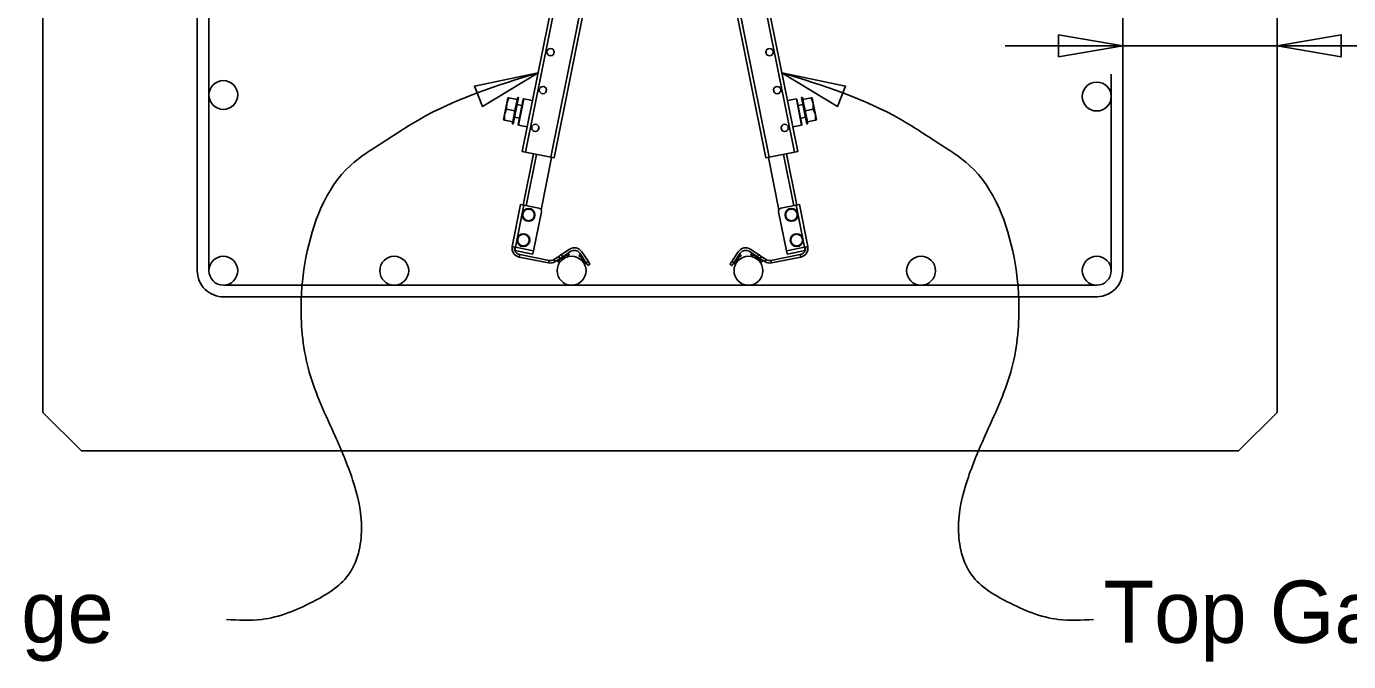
# Model space of a CAD drawing. Extents: x 0 to 36.1, y -3.7 to 15.
# Drawn here: x 2.266 to 4.409, y 2.071 to 3.1 of the extents above; entities that cross this region are included whole.
import ezdxf

# ---------------------------------------------------------------- set-up
doc = ezdxf.new("R2010")
doc.units = 0
for name, color, linetype in [('Leader', 7, 'Continuous'), ('Miscellaneous', 7, 'Continuous'), ('PileConc', 7, 'Continuous'), ('PlotBorder_dp', 7, 'Continuous'), ('PrestressSteel', 7, 'Continuous')]:
    doc.layers.add(name, color=color, linetype=linetype)

msp = doc.modelspace()

# ---------------------------------------------------------------- linework, layer by layer
at = {"layer": 'Leader'}
for points in [[(2.5903, 2.1388), (2.6477, 2.1388), (2.7303, 2.1675), (2.7877, 2.2106), (2.8093, 2.2859), (2.7949, 2.3649), (2.7662, 2.4367), (2.7246, 2.5398), (2.7114, 2.6484), (2.7193, 2.7252), (2.7913, 2.8747), (2.8439, 2.912), (2.903, 2.9492), (3.0957, 3.0249)], [(3.9958, 2.1388), (3.9383, 2.1388), (3.8558, 2.1675), (3.7983, 2.2106), (3.7768, 2.2859), (3.7912, 2.3649), (3.8199, 2.4367), (3.8615, 2.5398), (3.8747, 2.6484), (3.8668, 2.7252), (3.7947, 2.8747), (3.7422, 2.912), (3.6831, 2.9492), (3.4904, 3.0249)]]:
    msp.add_spline(points, degree=3, dxfattribs=at)
at = {"layer": 'Miscellaneous'}
for p, q in [((3.5162, 2.8971), (3.3195, 3.8739)), ((3.0699, 2.8971), (3.2126, 3.6058)), ((3.0751, 2.896), (3.1768, 3.4012)), ((3.1161, 2.8878), (3.2173, 3.3902)), ((3.1213, 2.8867), (3.2224, 3.3892)), ((3.4648, 2.8867), (3.3637, 3.3892)), ((3.47, 2.8878), (3.3688, 3.3902)), ((3.511, 2.896), (3.4093, 3.4012)), ((3.1203, 3.0546), (3.1214, 3.0597)), ((3.4658, 3.0546), (3.4647, 3.0597)), ((3.0447, 2.9753), (3.0465, 2.9843)), ((3.0481, 2.984), (3.0447, 2.9753)), ((3.0465, 2.9843), (3.0481, 2.984)), ((3.0615, 2.9813), (3.0481, 2.984)), ((3.0624, 2.9848), (3.0538, 2.9418)), ((3.055, 2.9416), (3.0636, 2.9846)), ((3.0615, 2.9813), (3.0579, 2.9633)), ((3.0611, 2.9814), (3.0624, 2.9848)), ((3.0624, 2.9848), (3.0636, 2.9846)), ((3.0713, 2.9821), (3.063, 2.9409)), ((3.0635, 2.9401), (3.0721, 2.9826)), ((3.0721, 2.9826), (3.0866, 2.9797)), ((3.108, 2.9932), (3.109, 2.9984)), ((3.4781, 2.9932), (3.4771, 2.9984)), ((3.514, 2.9826), (3.4995, 2.9797)), ((3.5226, 2.9401), (3.514, 2.9826)), ((3.5148, 2.9821), (3.5231, 2.9409)), ((3.5237, 2.9848), (3.5225, 2.9846)), ((3.5311, 2.9416), (3.5225, 2.9846)), ((3.525, 2.9814), (3.5237, 2.9848)), ((3.5237, 2.9848), (3.5323, 2.9418)), ((3.5245, 2.9813), (3.5379, 2.984)), ((3.5245, 2.9813), (3.5281, 2.9633)), ((3.5395, 2.9843), (3.5379, 2.984)), ((3.5379, 2.984), (3.5413, 2.9753)), ((3.5413, 2.9753), (3.5395, 2.9843)), ((3.0393, 2.9485), (3.0411, 2.9574)), ((3.0411, 2.9574), (3.0447, 2.9753)), ((3.0445, 2.966), (3.0411, 2.9574)), ((3.0579, 2.9633), (3.0445, 2.966)), ((3.0579, 2.9633), (3.0543, 2.9454)), ((3.0614, 2.9733), (3.0692, 2.9717)), ((3.5247, 2.9733), (3.5169, 2.9717)), ((3.5281, 2.9633), (3.5415, 2.966)), ((3.5281, 2.9633), (3.5318, 2.9454)), ((3.545, 2.9574), (3.5413, 2.9753)), ((3.5415, 2.966), (3.545, 2.9574)), ((3.5468, 2.9485), (3.545, 2.9574)), ((3.0409, 2.9481), (3.0393, 2.9485)), ((3.0543, 2.9454), (3.0409, 2.9481)), ((3.0538, 2.9418), (3.0538, 2.9455)), ((3.055, 2.9416), (3.0538, 2.9418)), ((3.0651, 2.9513), (3.0572, 2.9528)), ((3.078, 2.9372), (3.0635, 2.9401)), ((3.0956, 2.9318), (3.0966, 2.937)), ((3.4905, 2.9318), (3.4894, 2.937)), ((3.5081, 2.9372), (3.5226, 2.9401)), ((3.521, 2.9513), (3.5288, 2.9528)), ((3.5311, 2.9416), (3.5323, 2.9418)), ((3.5318, 2.9454), (3.5452, 2.9481)), ((3.5323, 2.9418), (3.5322, 2.9455)), ((3.5452, 2.9481), (3.5468, 2.9485)), ((3.0751, 2.896), (3.0699, 2.8971)), ((3.0712, 2.8104), (3.0879, 2.8934)), ((3.0751, 2.896), (3.1161, 2.8878)), ((3.511, 2.896), (3.47, 2.8878)), ((3.5149, 2.8104), (3.4982, 2.8934)), ((3.511, 2.896), (3.5162, 2.8971)), ((3.0763, 2.8093), (3.093, 2.8924)), ((3.1003, 2.8028), (3.1173, 2.8875)), ((3.1213, 2.8867), (3.1161, 2.8878)), ((3.4648, 2.8867), (3.47, 2.8878)), ((3.4858, 2.8028), (3.4687, 2.8875)), ((3.5098, 2.8093), (3.493, 2.8924)), ((3.0535, 2.7431), (3.0672, 2.8112)), ((3.0587, 2.7421), (3.0724, 2.8101)), ((3.0672, 2.8112), (3.0724, 2.8101)), ((3.0969, 2.8052), (3.0724, 2.8101)), ((3.4891, 2.8052), (3.5137, 2.8101)), ((3.5189, 2.8112), (3.5137, 2.8101)), ((3.5274, 2.7421), (3.5137, 2.8101)), ((3.5326, 2.7431), (3.5189, 2.8112)), ((3.0882, 2.7362), (3.1009, 2.7993)), ((3.4979, 2.7362), (3.4852, 2.7993)), ((3.0587, 2.7421), (3.0535, 2.7431)), ((3.5274, 2.7421), (3.5326, 2.7431)), ((3.0577, 2.7369), (3.0587, 2.7421)), ((3.0871, 2.731), (3.0577, 2.7369)), ((3.0587, 2.7421), (3.0882, 2.7362)), ((3.0656, 2.7301), (3.0648, 2.7261)), ((3.1124, 2.7166), (3.0648, 2.7261)), ((3.1132, 2.7205), (3.0656, 2.7301)), ((3.0882, 2.7362), (3.0871, 2.731)), ((3.1289, 2.7273), (3.121, 2.722)), ((3.121, 2.722), (3.1232, 2.7187)), ((3.1311, 2.7239), (3.1232, 2.7187)), ((3.1311, 2.7239), (3.1289, 2.7273)), ((3.1296, 2.7214), (3.1307, 2.7197)), ((3.1462, 2.7388), (3.133, 2.73)), ((3.133, 2.73), (3.1353, 2.7267)), ((3.1337, 2.7242), (3.1349, 2.7225)), ((3.1353, 2.7267), (3.1485, 2.7355)), ((3.136, 2.7272), (3.1367, 2.7261)), ((3.1362, 2.7258), (3.1374, 2.7241)), ((3.1379, 2.727), (3.1391, 2.7252)), ((3.1421, 2.7297), (3.1432, 2.728)), ((3.1443, 2.7327), (3.145, 2.7317)), ((3.1446, 2.7314), (3.1457, 2.7296)), ((3.1633, 2.7298), (3.1615, 2.7287)), ((3.1629, 2.7326), (3.1736, 2.7166)), ((3.163, 2.7303), (3.164, 2.731)), ((3.1649, 2.7274), (3.1632, 2.7262)), ((3.1665, 2.725), (3.1648, 2.7238)), ((3.1662, 2.7254), (3.1672, 2.7261)), ((3.1769, 2.7188), (3.1663, 2.7348)), ((3.1681, 2.7225), (3.1664, 2.7213)), ((3.4092, 2.7188), (3.4198, 2.7348)), ((3.4232, 2.7326), (3.4125, 2.7166)), ((3.418, 2.7225), (3.4197, 2.7213)), ((3.4199, 2.7254), (3.4189, 2.7261)), ((3.4196, 2.725), (3.4213, 2.7238)), ((3.4212, 2.7274), (3.4229, 2.7262)), ((3.4231, 2.7303), (3.4221, 2.731)), ((3.4228, 2.7298), (3.4246, 2.7287)), ((3.4508, 2.7267), (3.4376, 2.7355)), ((3.4398, 2.7388), (3.4531, 2.73)), ((3.4415, 2.7314), (3.4404, 2.7296)), ((3.4418, 2.7327), (3.4411, 2.7317)), ((3.444, 2.7297), (3.4428, 2.728)), ((3.4482, 2.727), (3.447, 2.7252)), ((3.4499, 2.7258), (3.4487, 2.7241)), ((3.4501, 2.7272), (3.4494, 2.7261)), ((3.4531, 2.73), (3.4508, 2.7267)), ((3.4523, 2.7242), (3.4512, 2.7225)), ((3.455, 2.7239), (3.4572, 2.7273)), ((3.455, 2.7239), (3.4629, 2.7187)), ((3.4565, 2.7214), (3.4554, 2.7197)), ((3.4572, 2.7273), (3.4651, 2.722)), ((3.4651, 2.722), (3.4629, 2.7187)), ((3.4729, 2.7205), (3.5204, 2.7301)), ((3.4737, 2.7166), (3.5212, 2.7261)), ((3.5274, 2.7421), (3.4979, 2.7362)), ((3.4979, 2.7362), (3.499, 2.731)), ((3.499, 2.731), (3.5284, 2.7369)), ((3.5204, 2.7301), (3.5212, 2.7261)), ((3.5284, 2.7369), (3.5274, 2.7421)), ((3.1124, 2.7166), (3.1132, 2.7205)), ((3.1267, 2.7195), (3.126, 2.7205)), ((3.1271, 2.7198), (3.1283, 2.718)), ((3.1693, 2.7207), (3.1676, 2.7196)), ((3.1709, 2.7183), (3.1692, 2.7172)), ((3.1725, 2.7159), (3.1708, 2.7147)), ((3.1739, 2.7161), (3.1728, 2.7154)), ((3.1736, 2.7166), (3.1769, 2.7188)), ((3.1797, 2.7146), (3.1763, 2.7124)), ((3.4064, 2.7146), (3.4097, 2.7124)), ((3.4125, 2.7166), (3.4092, 2.7188)), ((3.4122, 2.7161), (3.4132, 2.7154)), ((3.4135, 2.7159), (3.4153, 2.7147)), ((3.4152, 2.7183), (3.4169, 2.7172)), ((3.4168, 2.7207), (3.4185, 2.7196)), ((3.459, 2.7198), (3.4578, 2.718)), ((3.4594, 2.7195), (3.4601, 2.7205)), ((3.4737, 2.7166), (3.4729, 2.7205))]:
    msp.add_line(p, q, dxfattribs=at)
for points in [[(3.0411, 2.9574), (3.041, 2.9568), (3.0409, 2.9481)], [(3.0447, 2.9753), (3.0446, 2.9747), (3.0445, 2.966)], [(3.5413, 2.9753), (3.5415, 2.9747), (3.5415, 2.966)], [(3.545, 2.9574), (3.5451, 2.9568), (3.5452, 2.9481)], [(3.1289, 2.7273), (3.1289, 2.7273), (3.1292, 2.7275), (3.1296, 2.7277), (3.1301, 2.7281), (3.1307, 2.7285), (3.1314, 2.729), (3.1322, 2.7295), (3.133, 2.73)], [(3.1337, 2.7242), (3.1332, 2.7239), (3.1327, 2.7235), (3.1322, 2.7232), (3.1317, 2.7228), (3.1311, 2.7225), (3.1306, 2.7221), (3.1301, 2.7218), (3.1296, 2.7214)], [(3.1353, 2.7267), (3.1344, 2.7262), (3.1337, 2.7256), (3.1329, 2.7252), (3.1323, 2.7247), (3.1318, 2.7244), (3.1314, 2.7241), (3.1312, 2.724), (3.1311, 2.7239)], [(3.1374, 2.7241), (3.1372, 2.724), (3.1369, 2.7238), (3.1367, 2.7236), (3.1364, 2.7234), (3.136, 2.7232), (3.1357, 2.723), (3.1353, 2.7227), (3.1349, 2.7225)], [(3.1367, 2.7261), (3.1366, 2.7261), (3.1366, 2.7261), (3.1364, 2.726), (3.1362, 2.7258)], [(3.1391, 2.7252), (3.1387, 2.725), (3.1383, 2.7247), (3.138, 2.7245), (3.1376, 2.7243), (3.1374, 2.7241)], [(3.1421, 2.7297), (3.1416, 2.7294), (3.1411, 2.7291), (3.1405, 2.7287), (3.14, 2.7284), (3.1395, 2.728), (3.1389, 2.7277), (3.1384, 2.7273), (3.1379, 2.727)], [(3.1457, 2.7296), (3.1455, 2.7295), (3.1453, 2.7294), (3.145, 2.7292), (3.1447, 2.729), (3.1444, 2.7288), (3.144, 2.7285), (3.1436, 2.7283), (3.1432, 2.728)], [(3.145, 2.7317), (3.145, 2.7317), (3.1449, 2.7316), (3.1448, 2.7315), (3.1446, 2.7314)], [(3.1632, 2.7262), (3.1629, 2.7266), (3.1626, 2.727), (3.1624, 2.7273), (3.1622, 2.7277), (3.162, 2.728), (3.1618, 2.7282), (3.1617, 2.7285), (3.1615, 2.7287)], [(3.1633, 2.7298), (3.1631, 2.73), (3.163, 2.7302), (3.163, 2.7303), (3.163, 2.7303)], [(3.1664, 2.7213), (3.1661, 2.7217), (3.1659, 2.7221), (3.1656, 2.7225), (3.1654, 2.7228), (3.1652, 2.7231), (3.165, 2.7234), (3.1649, 2.7236), (3.1648, 2.7238)], [(3.1662, 2.7254), (3.1659, 2.7258), (3.1656, 2.7263), (3.1652, 2.7269), (3.1649, 2.7274)], [(3.1665, 2.725), (3.1664, 2.7252), (3.1663, 2.7253), (3.1662, 2.7254), (3.1662, 2.7254)], [(3.1676, 2.7196), (3.1674, 2.7198), (3.1673, 2.72), (3.1671, 2.7203), (3.1669, 2.7206), (3.1667, 2.7209), (3.1664, 2.7213), (3.1664, 2.7213)], [(3.1709, 2.7183), (3.1706, 2.7188), (3.1702, 2.7193), (3.1699, 2.7199), (3.1695, 2.7204), (3.1692, 2.7209), (3.1688, 2.7215), (3.1685, 2.722), (3.1681, 2.7225)], [(3.4152, 2.7183), (3.4155, 2.7188), (3.4159, 2.7193), (3.4162, 2.7199), (3.4166, 2.7204), (3.4169, 2.7209), (3.4173, 2.7215), (3.4176, 2.722), (3.418, 2.7225)], [(3.4185, 2.7196), (3.4186, 2.7198), (3.4188, 2.72), (3.419, 2.7203), (3.4192, 2.7206), (3.4194, 2.7209), (3.4196, 2.7213), (3.4197, 2.7213)], [(3.4196, 2.725), (3.4197, 2.7252), (3.4198, 2.7253), (3.4199, 2.7254), (3.4199, 2.7254)], [(3.4197, 2.7213), (3.42, 2.7217), (3.4202, 2.7221), (3.4204, 2.7225), (3.4207, 2.7228), (3.4209, 2.7231), (3.421, 2.7234), (3.4212, 2.7236), (3.4213, 2.7238)], [(3.4199, 2.7254), (3.4202, 2.7258), (3.4205, 2.7263), (3.4209, 2.7269), (3.4212, 2.7274)], [(3.4228, 2.7298), (3.423, 2.73), (3.4231, 2.7302), (3.4231, 2.7303), (3.4231, 2.7303)], [(3.4229, 2.7262), (3.4232, 2.7266), (3.4234, 2.727), (3.4237, 2.7273), (3.4239, 2.7277), (3.4241, 2.728), (3.4243, 2.7282), (3.4244, 2.7285), (3.4246, 2.7287)], [(3.4404, 2.7296), (3.4406, 2.7295), (3.4408, 2.7294), (3.4411, 2.7292), (3.4414, 2.729), (3.4417, 2.7288), (3.4421, 2.7285), (3.4424, 2.7283), (3.4428, 2.728)], [(3.4411, 2.7317), (3.4411, 2.7317), (3.4412, 2.7316), (3.4413, 2.7315), (3.4415, 2.7314)], [(3.444, 2.7297), (3.4445, 2.7294), (3.445, 2.7291), (3.4455, 2.7287), (3.4461, 2.7284), (3.4466, 2.728), (3.4471, 2.7277), (3.4477, 2.7273), (3.4482, 2.727)], [(3.447, 2.7252), (3.4474, 2.725), (3.4478, 2.7247), (3.4481, 2.7245), (3.4485, 2.7243), (3.4487, 2.7241)], [(3.4487, 2.7241), (3.4489, 2.724), (3.4492, 2.7238), (3.4494, 2.7236), (3.4497, 2.7234), (3.4501, 2.7232), (3.4504, 2.723), (3.4508, 2.7227), (3.4512, 2.7225)], [(3.4494, 2.7261), (3.4494, 2.7261), (3.4495, 2.7261), (3.4497, 2.726), (3.4499, 2.7258)], [(3.4508, 2.7267), (3.4516, 2.7262), (3.4524, 2.7256), (3.4531, 2.7252), (3.4538, 2.7247), (3.4543, 2.7244), (3.4547, 2.7241), (3.4549, 2.724), (3.455, 2.7239)], [(3.4523, 2.7242), (3.4528, 2.7239), (3.4534, 2.7235), (3.4539, 2.7232), (3.4544, 2.7228), (3.455, 2.7225), (3.4555, 2.7221), (3.456, 2.7218), (3.4565, 2.7214)], [(3.4572, 2.7273), (3.4571, 2.7273), (3.4569, 2.7275), (3.4565, 2.7277), (3.456, 2.7281), (3.4554, 2.7285), (3.4546, 2.729), (3.4539, 2.7295), (3.4531, 2.73)], [(3.1271, 2.7198), (3.1269, 2.7197), (3.1268, 2.7196), (3.1267, 2.7195), (3.1267, 2.7195)], [(3.1307, 2.7197), (3.1303, 2.7194), (3.13, 2.7192), (3.1296, 2.7189), (3.1293, 2.7187), (3.129, 2.7185), (3.1287, 2.7183), (3.1285, 2.7182), (3.1283, 2.718)], [(3.1708, 2.7147), (3.1707, 2.7149), (3.1705, 2.7151), (3.1703, 2.7154), (3.1701, 2.7157), (3.1699, 2.716), (3.1697, 2.7164), (3.1694, 2.7168), (3.1692, 2.7172)], [(3.1728, 2.7154), (3.1728, 2.7154), (3.1728, 2.7155), (3.1727, 2.7157), (3.1725, 2.7159)], [(3.1763, 2.7124), (3.1763, 2.7125), (3.1761, 2.7127), (3.1759, 2.7131), (3.1755, 2.7136), (3.1751, 2.7143), (3.1746, 2.715), (3.1741, 2.7158), (3.1736, 2.7166)], [(3.1769, 2.7188), (3.1774, 2.718), (3.178, 2.7172), (3.1784, 2.7165), (3.1789, 2.7159), (3.1792, 2.7153), (3.1795, 2.7149), (3.1796, 2.7147), (3.1797, 2.7146)], [(3.4092, 2.7188), (3.4086, 2.718), (3.4081, 2.7172), (3.4076, 2.7165), (3.4072, 2.7159), (3.4069, 2.7153), (3.4066, 2.7149), (3.4065, 2.7147), (3.4064, 2.7146)], [(3.4097, 2.7124), (3.4098, 2.7125), (3.41, 2.7127), (3.4102, 2.7131), (3.4106, 2.7136), (3.411, 2.7143), (3.4115, 2.715), (3.412, 2.7158), (3.4125, 2.7166)], [(3.4132, 2.7154), (3.4133, 2.7154), (3.4133, 2.7155), (3.4134, 2.7157), (3.4135, 2.7159)], [(3.4153, 2.7147), (3.4154, 2.7149), (3.4156, 2.7151), (3.4158, 2.7154), (3.4159, 2.7157), (3.4162, 2.716), (3.4164, 2.7164), (3.4167, 2.7168), (3.4169, 2.7172)], [(3.4554, 2.7197), (3.4557, 2.7194), (3.4561, 2.7192), (3.4565, 2.7189), (3.4568, 2.7187), (3.4571, 2.7185), (3.4574, 2.7183), (3.4576, 2.7182), (3.4578, 2.718)], [(3.459, 2.7198), (3.4592, 2.7197), (3.4593, 2.7196), (3.4594, 2.7195), (3.4594, 2.7195)]]:
    msp.add_lwpolyline(points, dxfattribs=at)
for centre, radius in [((3.1157, 3.0582), 0.00589), ((3.4704, 3.0582), 0.00589), ((3.1033, 2.9968), 0.00589), ((3.4828, 2.9968), 0.00589), ((3.091, 2.9354), 0.00589), ((3.4951, 2.9354), 0.00589), ((3.08, 2.7945), 0.0104), ((3.08, 2.7945), 0.00951), ((3.5061, 2.7945), 0.0104), ((3.5061, 2.7945), 0.00951), ((3.0717, 2.7536), 0.0104), ((3.0717, 2.7536), 0.00951), ((3.5144, 2.7536), 0.0104), ((3.5144, 2.7536), 0.00951)]:
    msp.add_circle(centre, radius, dxfattribs=at)
for centre, radius, start, end in [((3.072, 2.982), 0.000668, 78.6185, 168.6185), ((3.5141, 2.982), 0.000668, 11.3815, 101.3815), ((3.0636, 2.9407), 0.000668, 168.6185, 258.6185), ((3.5224, 2.9407), 0.000668, 281.3815, 11.3815), ((3.096, 2.8003), 0.00501, 348.6185, 78.6185), ((3.4901, 2.8003), 0.00501, 101.3815, 191.3815), ((3.0677, 2.7403), 0.0144, 168.6185, 258.6185), ((3.5184, 2.7403), 0.0144, 281.3815, 11.3815), ((3.0677, 2.7403), 0.0104, 168.6185, 196.9761), ((3.0677, 2.7403), 0.0104, 198.8835, 258.6185), ((3.1152, 2.7307), 0.0104, 258.6185, 303.6185), ((3.1542, 2.7268), 0.0144, 33.6185, 123.6185), ((3.1542, 2.7268), 0.0104, 33.6185, 123.6185), ((3.4318, 2.7268), 0.0144, 56.3815, 146.3815), ((3.4318, 2.7268), 0.0104, 56.3815, 146.3815), ((3.4709, 2.7307), 0.0104, 236.3815, 281.3815), ((3.5184, 2.7403), 0.0104, 281.3815, 341.1165), ((3.5184, 2.7403), 0.0104, 343.0239, 11.3815), ((3.1152, 2.7307), 0.0144, 258.6185, 303.6185), ((3.4709, 2.7307), 0.0144, 236.3815, 281.3815)]:
    msp.add_arc(centre, radius, start, end, dxfattribs=at)
at = {"layer": 'PileConc'}
for p, q in [((2.293, 4.3493), (2.293, 2.4743)), ((4.293, 4.3493), (4.293, 2.4743)), ((2.3555, 2.4118), (2.293, 2.4743)), ((4.293, 2.4743), (4.2305, 2.4118)), ((2.3555, 2.4118), (4.2305, 2.4118))]:
    msp.add_line(p, q, dxfattribs=at)
at = {"layer": 'PlotBorder_dp'}
for p, q in [((3.8524, 3.0685), (4.043, 3.0685)), ((4.043, 3.0685), (4.293, 3.0685)), ((4.293, 3.0685), (5.1697, 3.0685))]:
    msp.add_line(p, q, dxfattribs=at)
for points in [[(4.043, 3.0685), (3.9389, 3.0861), (3.9389, 3.0508)], [(4.293, 3.0685), (4.3972, 3.0508), (4.3972, 3.0861)], [(3.0957, 3.0249), (2.9923, 3.0032), (3.0052, 2.9704)], [(3.4904, 3.0249), (3.5809, 2.9704), (3.5938, 3.0032)]]:
    msp.add_lwpolyline(points, close=True, dxfattribs=at)
at = {"layer": 'PrestressSteel'}
for p, q in [((2.543, 4.1196), (2.543, 2.704)), ((2.5618, 4.1196), (2.5618, 2.704)), ((4.043, 3.7277), (4.043, 2.704)), ((4.0242, 3.0227), (4.0242, 2.704)), ((2.5861, 2.6806), (4, 2.6806)), ((2.5862, 2.6618), (4.0017, 2.6618))]:
    msp.add_line(p, q, dxfattribs=at)
for centre in [(2.5853, 2.9888), (4.0008, 2.9863), (2.5853, 2.704), (2.8623, 2.704), (3.1497, 2.704), (3.4364, 2.704), (3.7161, 2.704), (4.0008, 2.704)]:
    msp.add_circle(centre, 0.0234, dxfattribs=at)
for centre, start, end in [((2.5853, 2.704), 180, 271.2723), ((4.0008, 2.704), 271.2723, 0)]:
    msp.add_arc(centre, 0.0423, start, end, dxfattribs=at)

# ---------------------------------------------------------------- texts
at = {"layer": 'PlotBorder_dp'}
for s, p in [('Tip Gauge', (1.7783, 2.1009)), ('Top Gauge', (4.0115, 2.1009))]:
    msp.add_text(s, height=0.1008, dxfattribs=at).set_placement(p)

doc.saveas('drawing.dxf')
